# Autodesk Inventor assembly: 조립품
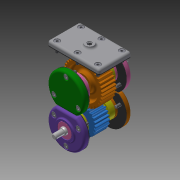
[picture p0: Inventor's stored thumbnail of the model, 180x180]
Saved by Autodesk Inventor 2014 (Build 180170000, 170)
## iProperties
Created: 2020-05
Part Number: 조립품
Document SubType Name: Assembly
Designer: kh
Author: kh
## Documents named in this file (24)
- C:\Users\kh\Desktop\600506V1033\조립품.iam
- C:\Users\kh\Desktop\600506V1033\본체.ipt
- C:\Users\kh\Desktop\600506V1033\개스킷 A.ipt
- C:\Users\kh\Desktop\600506V1033\개스킷 B.ipt
- C:\Users\kh\Desktop\600506V1033\개스킷 C.ipt
- C:\Users\kh\Desktop\600506V1033\베어링 6001.ipt
- 베어링 6001.ipt
- C:\Users\kh\Desktop\600506V1033\베어링 6002.ipt
- 베어링 6002.ipt
- C:\Users\kh\Desktop\600506V1033\볼트 M4.ipt
- C:\Users\kh\Desktop\600506V1033\스퍼기어 A.ipt
- C:\Users\kh\Desktop\600506V1033\스퍼기어 B.ipt
- C:\Users\kh\Desktop\600506V1033\오일 실 10 20 7.ipt
- C:\Users\kh\Desktop\600506V1033\오일 실 12 22 7.ipt
- C:\Users\kh\Desktop\600506V1033\축 A.ipt
- C:\Users\kh\Desktop\600506V1033\축 B.ipt
- C:\Users\kh\Desktop\600506V1033\칼라.ipt
- C:\Users\kh\Desktop\600506V1033\커버 A.ipt
- C:\Users\kh\Desktop\600506V1033\커버 B.ipt
- C:\Users\kh\Desktop\600506V1033\커버 C.ipt
- C:\Users\kh\Desktop\600506V1033\커버 D.ipt
- C:\Users\kh\Desktop\600506V1033\커버 E.ipt
- C:\Users\kh\Desktop\600506V1033\키 4 x 4 x 12.ipt
- C:\Users\kh\Desktop\600506V1033\키 5 x 5 x 12.ipt
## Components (5 placed, 3 different names)
1. 개스킷 A:1
2. 개스킷 C:1
3. 개스킷 B:1
4. 개스킷 B:2
5. 개스킷 B:3
